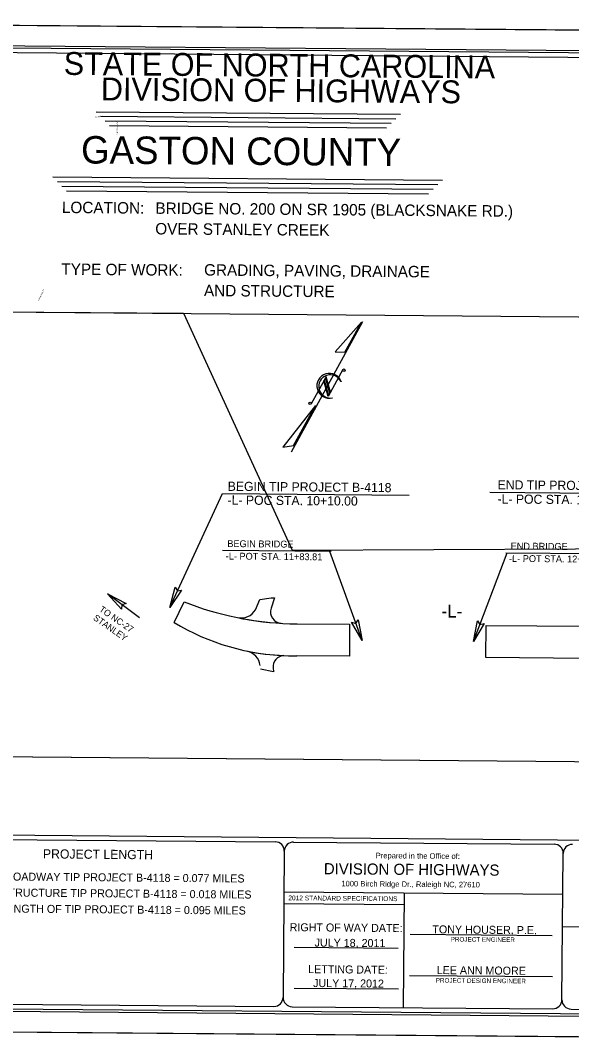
# Model space of a CAD drawing. Extents: x 1379453 to 1387082, y 594364 to 596664.
# Drawn here: x 1380803 to 1382008, y 594364 to 596592 of the extents above; entities that cross this region are included whole.
import ezdxf

# ---------------------------------------------------------------- set-up
doc = ezdxf.new("R2010")
doc.units = 0
for name, color, linetype in [('Old_Level_10', 7, 'Continuous'), ('Old_Level_32', 7, 'Continuous'), ('Prop Horizontal Alignment Station Label', 7, 'Continuous'), ('Prop Shade Medium', 7, 'Continuous'), ('Prop Terminator CELL', 7, 'Continuous'), ('Sheet Clip Boundary CELL', 7, 'Continuous'), ('Sheet Cutting Line CELL', 7, 'Continuous'), ('Sheet Data Field CELL', 7, 'Continuous'), ('Sheet North Arrow CELL', 7, 'Continuous'), ('Sheet Plot Border Inside CELL', 7, 'Continuous'), ('Sheet Plot Border Outside CELL', 7, 'Continuous'), ('Sheet Title CELL', 7, 'Continuous')]:
    doc.layers.add(name, color=color, linetype=linetype)

msp = doc.modelspace()

# ---------------------------------------------------------------- linework, layer by layer
at = {"layer": 'Old_Level_32'}
msp.add_lwpolyline([(1380751.9, 595954.7), (1382700.4, 595938.4), (1382692.2, 594965.7), (1380743.7, 594982)], close=True, dxfattribs=at)
at = {"layer": 'Prop Horizontal Alignment Station Label'}
for p, q in [((1381129.4, 595308.9), (1381244.8, 595557.6)), ((1381244.8, 595557.6), (1381653, 595554.2)), ((1382222.4, 595556.6), (1381829.5, 595559.9)), ((1381482.3, 595431.4), (1381244.9, 595433.4)), ((1381550, 595236.7), (1381479.4, 595431.4)), ((1381793.5, 595234.6), (1381867.4, 595428.2)), ((1381864.4, 595428.2), (1382101.9, 595426.2)), ((1381063.1, 595286.3), (1380993, 595338.4))]:
    msp.add_line(p, q, dxfattribs=at)
at = {"layer": 'Prop Shade Medium'}
for p, q in [((1381326.2, 595326.3), (1381351.3, 595329.7)), ((1381358.8, 595329.6), (1381351.1, 595307)), ((1381351.3, 595329.7), (1381358.8, 595329.6)), ((1381138.8, 595276.1), (1381160.7, 595321)), ((1381316.9, 595303.6), (1381326.2, 595326.3)), ((1381408.1, 595272.8), (1381522.8, 595271.9)), ((1381522.8, 595271.9), (1381522.2, 595201.9)), ((1381820.7, 595199.4), (1381821.3, 595269.4)), ((1381821.3, 595269.4), (1382043, 595267.5)), ((1381522.2, 595201.9), (1381407.5, 595202.8)), ((1382042.4, 595197.5), (1381820.7, 595199.4)), ((1381356.3, 595168.2), (1381328.1, 595173.7)), ((1381355.3, 595176.8), (1381356.3, 595168.2))]:
    msp.add_line(p, q, dxfattribs=at)
for centre, radius, start, end in [((1381413.5, 595960.4), 687.5, 248.4271, 268.1921), ((1381284.9, 595323.2), 37.5, 258.593, 328.5435), ((1381413.5, 595960.4), 687.5, 258.593, 266.653), ((1381374.8, 595299), 25, 161.2939, 266.653), ((1381398.8, 595703.2), 500, 238.6666, 268.9004), ((1381412.8, 595837.8), 565, 267.8701, 269.52), ((1381398.8, 595703.2), 500, 258.3117, 267.6837), ((1381289.9, 595176.8), 37.5, 7.2545, 78.3117), ((1381380.2, 595178.6), 25, 93.6658, 184.19), ((1381412.8, 595837.8), 635, 267.8701, 269.52)]:
    msp.add_arc(centre, radius, start, end, dxfattribs=at)
at = {"layer": 'Prop Terminator CELL'}
for points in [[(1381155.4, 595346.5), (1381129.4, 595308.9), (1381141.2, 595353.4), (1381146, 595344.8)], [(1381023.9, 595304.8), (1380993, 595338.4), (1381033.7, 595317.1), (1381024.3, 595314.3)], [(1381541.7, 595281.6), (1381550, 595236.7), (1381526.9, 595276.3), (1381536.4, 595273.7)], [(1381816.8, 595273.8), (1381793.5, 595234.6), (1381802.2, 595279.7), (1381807.6, 595271.5)]]:
    msp.add_lwpolyline(points, close=True, dxfattribs=at)
at = {"layer": 'Sheet Clip Boundary CELL'}
msp.add_lwpolyline([(1380751.9, 595954.7), (1381159.4, 595952.2), (1381397, 595433.8), (1382327, 595438.1), (1382414.4, 595940.9), (1382700.4, 595938.5), (1382692.2, 594965.7), (1380744.6, 594982)], close=True, dxfattribs=at)
at = {"layer": 'Sheet Cutting Line CELL'}
for p, q in [((1379471, 596592.1), (1382838.9, 596563.9)), ((1379452.6, 594392.2), (1382820.5, 594364))]:
    msp.add_line(p, q, dxfattribs=at)
at = {"layer": 'Sheet North Arrow CELL'}
for p, q in [((1381395.3, 595648.9), (1381551.8, 595933.7)), ((1381508, 595828.7), (1381475.9, 595770.2)), ((1381471.1, 595813.1), (1381438.5, 595753.7)), ((1381475.9, 595770.2), (1381466.1, 595804)), ((1381469.9, 595810.9), (1381467, 595805.6)), ((1381476.8, 595771.8), (1381467, 595805.6)), ((1381467, 595805.6), (1381476.8, 595771.8)), ((1381479.8, 595777.2), (1381469.9, 595810.9)), ((1381480.9, 595779.3), (1381471.1, 595813.1)), ((1381504.1, 595802.5), (1381504.3, 595802.1)), ((1381476.8, 595771.8), (1381479.8, 595777.2))]:
    msp.add_line(p, q, dxfattribs=at)
for points in [[(1381548.4, 595932.3), (1381491.5, 595867.2), (1381512.3, 595866.5)], [(1381448.1, 595750.5), (1381376.8, 595659), (1381399.9, 595662.8)]]:
    msp.add_lwpolyline(points, close=True, dxfattribs=at)
for centre in [(1381510.3, 595827.4), (1381436.1, 595754.8)]:
    msp.add_circle(centre, 2.65, dxfattribs=at)
for centre, radius, start, end in [((1381478.5, 595793.2), 27.3, 19.0551, 283.6092), ((1381480.8, 595791.9), 25.6, 24.3101, 279.8438)]:
    msp.add_arc(centre, radius, start, end, dxfattribs=at)
at = {"layer": 'Sheet Plot Border Inside CELL'}
msp.add_lwpolyline([(1379479, 594436.9), (1382811.8, 594409), (1382829.5, 596519.1), (1379496.6, 596547)], close=True, dxfattribs=at)
at = {"layer": 'Sheet Plot Border Outside CELL'}
msp.add_lwpolyline([(1382838.9, 596563.9), (1379471, 596592.1), (1379452.6, 594392.2), (1382820.5, 594364)], close=True, dxfattribs=at)
at = {"layer": 'Sheet Title CELL'}
for p, q in [((1380968.2, 596392.5), (1381633.7, 596386.9)), ((1380978.1, 596382.4), (1381623.6, 596377)), ((1380988, 596372.3), (1381613.5, 596367.1)), ((1380997.9, 596362.2), (1381603.4, 596357.2)), ((1380873.7, 596250.1), (1381725.7, 596242.9)), ((1380883.6, 596240), (1381715.6, 596233)), ((1380893.5, 596229.9), (1381705.5, 596223.1)), ((1380903.5, 596219.8), (1381695.4, 596213.2)), ((1379920.2, 594818.3), (1382760.1, 594794.5)), ((1380600.1, 594802.6), (1381360, 594796.2)), ((1381400, 594795.9), (1381970, 594791.1)), ((1381379.9, 594776.1), (1381377.2, 594456.1)), ((1381987.2, 594451), (1381989.9, 594771)), ((1381989.1, 594681.5), (1381379.1, 594686.6)), ((1381642.2, 594684.4), (1381640.1, 594433.9)), ((1381642, 594658.9), (1381378.9, 594661.1)), ((1381566.2, 594659.5), (1381566.2, 594659.5)), ((1381655.3, 594594.3), (1381965.5, 594591.7)), ((1381986.7, 594611.1), (1382428, 594607.4)), ((1381629.2, 594563.3), (1381401.7, 594565.2)), ((1381515.4, 594564.2), (1381515.4, 594564.2)), ((1381653.8, 594504.3), (1381966.3, 594501.7)), ((1381629.3, 594474.1), (1381401.8, 594476))]:
    msp.add_line(p, q, dxfattribs=at)
for points in [[(1382784.5, 596514.4), (1379824.6, 596539.2)], [(1382774.4, 596504.4), (1379934.5, 596528.2)], [(1379807, 594439.2), (1382766.9, 594414.4)], [(1380597.1, 594442.6), (1381357, 594436.2)], [(1381397, 594435.9), (1381967, 594431.1)], [(1382007, 594430.8), (1382406.5, 594427.5)]]:
    msp.add_lwpolyline(points, dxfattribs=at)
for centre, start, end in [((1381359.9, 594776.3), 359.52, 89.52), ((1381399.9, 594776), 89.52, 179.52), ((1381969.9, 594771.2), 359.52, 89.52), ((1382009.9, 594770.9), 89.52, 179.52), ((1381357.2, 594456.4), 269.52, 359.52), ((1381397.2, 594456), 179.52, 269.52), ((1381967.2, 594451.3), 269.52, 359.52), ((1382007.2, 594450.9), 179.52, 269.52)]:
    msp.add_arc(centre, 20, start, end, dxfattribs=at)

# ---------------------------------------------------------------- texts
at = {"layer": 'Old_Level_10'}
for s, height, rotation, p in [('Franklin Ct', 2.625, 4.6887, (1380967.2, 596379.6)), ('Grand Canyon Rd', 2.625, 87.4377, (1381014.9, 596341.3)), ('White Oak Trl', 3.281, 64.5404, (1380843.6, 595978.5))]:
    msp.add_text(s, height=height, rotation=rotation, dxfattribs=at).set_placement(p)
at = {"layer": 'Prop Horizontal Alignment Station Label'}
for s, height, rotation, p in [('BEGIN TIP PROJECT B-4118', 20, 359.52, (1381256, 595563.7)), ('END TIP PROJECT B-4118', 20, 359.52, (1381846.4, 595567)), ('-L- POC STA. 10+10.00', 20, 359.52, (1381255.8, 595533.7)), ('-L- POC STA. 15+10.00', 20, 359.52, (1381846.2, 595536)), ('BEGIN BRIDGE', 15, 359.52, (1381255.2, 595440.8)), ('END BRIDGE', 15, 359.52, (1381874.8, 595435.6)), ('-L- POT STA. 11+83.81', 15, 359.52, (1381251.7, 595413.6)), ('-L- POT STA. 12+81.19', 15, 359.52, (1381871.3, 595408.4)), ('TO NC-27', 14, 325.3229, (1380973.7, 595301.6)), ('-L-', 28, 359.52, (1381723.6, 595286.9)), ('STANLEY', 14, 325.3229, (1380960.7, 595282.9))]:
    msp.add_text(s, height=height, rotation=rotation, dxfattribs=at).set_placement(p)
at = {"layer": 'Sheet Data Field CELL'}
for s, height, p in [('GASTON COUNTY', 60, (1380935.2, 596279.4)), ('BRIDGE NO. 200 ON SR 1905 (BLACKSNAKE RD.)', 25, (1381098, 596169.3)), ('OVER STANLEY CREEK', 25, (1381097.6, 596124.3)), ('GRADING, PAVING, DRAINAGE', 25, (1381204.4, 596034.3)), ('AND STRUCTURE', 25, (1381204.1, 595989.3)), ('LENGTH OF ROADWAY TIP PROJECT B-4118 = 0.077 MILES', 17.5, (1380629, 594713)), ('LENGTH OF STRUCTURE TIP PROJECT B-4118 = 0.018 MILES', 17.5, (1380620.8, 594678.1)), ('TOTAL LENGTH OF TIP PROJECT B-4118 = 0.095 MILES', 17.5, (1380677.2, 594642.6)), ('TONY HOUSER, P.E.', 17.5, (1381703.7, 594596.4)), ('JULY 18, 2011', 17.5, (1381446.1, 594567.4)), ('LEE ANN MOORE', 17.5, (1381713.1, 594507.3)), ('JULY 17, 2012', 17.5, (1381442.9, 594479))]:
    msp.add_text(s, height=height, rotation=359.52, dxfattribs=at).set_placement(p)
at = {"layer": 'Sheet Title CELL'}
for s, height, p in [('STATE OF NORTH CAROLINA', 50, (1380897.3, 596473)), ('DIVISION OF HIGHWAYS', 50, (1380978.6, 596417.3)), ('LOCATION: ', 25, (1380893.4, 596171)), ('TYPE OF WORK:', 25, (1380892.3, 596036)), ('PROJECT LENGTH', 19.999, (1380851.9, 594760.2)), ('Prepared in the Office of:', 11.999, (1381579.7, 594760.5)), ('DIVISION OF HIGHWAYS', 24.374, (1381466.4, 594725.5)), ('1000 Birch Ridge Dr., Raleigh NC, 27610', 12, (1381504.6, 594699.2)), ('2012 STANDARD SPECIFICATIONS', 10.4, (1381388.7, 594668.7)), ('RIGHT OF WAY DATE: ', 17.5, (1381391.5, 594601.1)), ('PROJECT ENGINEER', 9.999, (1381743.8, 594578.5)), ('LETTING DATE:', 17.5, (1381432, 594509.4)), ('PROJECT DESIGN ENGINEER', 9.999, (1381711.1, 594488.7))]:
    msp.add_text(s, height=height, rotation=359.52, dxfattribs=at).set_placement(p)

doc.saveas('drawing.dxf')
